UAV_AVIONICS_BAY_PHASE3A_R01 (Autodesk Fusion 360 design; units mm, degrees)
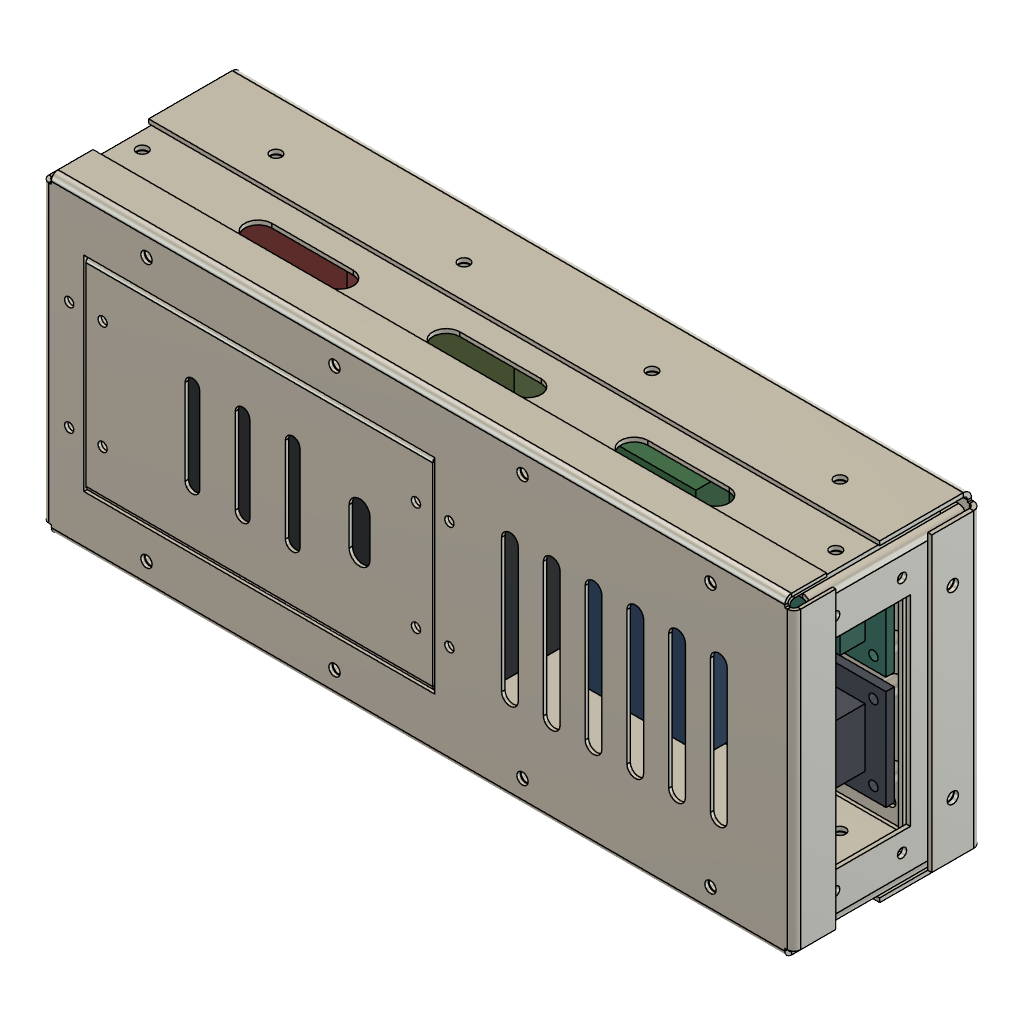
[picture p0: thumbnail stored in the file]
part number: 2026-11-24-00-04-00-130
part number: 2026-11-24-00-04-00-335
part number: 2026-11-24-00-04-00-357
part number: 2026-11-24-00-04-00-366
part number: 2026-11-24-00-04-00-376
part number: 2026-11-24-00-04-00-385
part number: 2026-11-24-00-04-00-395
part number: 2026-11-24-00-04-00-403
part number: 2026-11-24-00-04-00-413
part number: 2026-11-24-00-04-00-460
part number: 2026-11-24-00-04-01-313
part number: 2026-11-24-00-04-01-758
part number: 2026-11-24-00-04-02-270
part number: 2026-11-24-00-04-02-858
part number: 2026-11-24-00-04-03-521
part number: 2026-11-24-00-04-04-556
part number: 2026-11-24-00-04-05-190
part number: 2026-11-24-00-04-05-589
part number: 2026-11-24-00-04-06-393
part number: 2026-11-24-00-04-06-725
parameter "BAY_LENGTH" = 180 comment "[Assumption] Concept avionics bay overall outer length (X)"
parameter "BAY_WIDTH" = 75 comment "[Assumption] Concept avionics bay overall outer width (Y)"
parameter "BAY_HEIGHT" = 45 comment "[Assumption] Concept avionics bay overall outer height (Z)"
parameter "TRAY_FLANGE_H" = 22 comment "[Preliminary] Base tray perimeter upward flange height"
parameter "COVER_SKIRT_H" = 10 comment "[Preliminary] Top cover downward perimeter skirt height"
parameter "FORWARD_ZONE_END_X" = 94 comment "[Preliminary] X-boundary separating battery zone and aft deck"
parameter "HATCH_LENGTH" = 84 comment "[Preliminary] Service access hatch opening length"
parameter "HATCH_WIDTH" = 49 comment "[Preliminary] Service access hatch opening width"
parameter "T_BASE_TRAY" = 1 comment "[Preliminary] Main folded base tray thickness"
parameter "T_TOP_COVER" = 0.8 comment "[Preliminary] Removable top cover thickness"
parameter "T_ACCESS_HATCH" = 0.8 comment "[Preliminary] Service access hatch thickness"
parameter "T_SIDE_RAIL" = 1 comment "[Preliminary] Left and right side support rails thickness"
parameter "T_BULKHEAD" = 1 comment "[Preliminary] Front, rear, and connector bulkheads thickness"
parameter "T_EQUIP_DECK" = 1 comment "[Preliminary] Removable internal equipment deck thickness"
parameter "T_BRACKET" = 1 comment "[Preliminary] Structural and retention brackets thickness"
parameter "T_CABLE_CH" = 0.8 comment "[Preliminary] Cable routing channel and clamp thickness"
parameter "BEND_R_1_0" = 1 comment "[Preliminary] Inside bend radius for 1.0 mm Al 5052-H32"
parameter "BEND_R_0_8" = 0.8 comment "[Preliminary] Inside bend radius for 0.8 mm Al 5052-H32"
parameter "RELIEF_W_1_0" = 1.5 comment "[Preliminary] Bend relief width for 1.0 mm sheet"
parameter "RELIEF_D_1_0" = 2.5 comment "[Preliminary] Bend relief depth for 1.0 mm sheet"
parameter "RELIEF_W_0_8" = 1.2 comment "[Preliminary] Bend relief width for 0.8 mm sheet"
parameter "RELIEF_D_0_8" = 2.1 comment "[Preliminary] Bend relief depth for 0.8 mm sheet"
parameter "HOLE_CLR_M2_0" = 2.2 comment "[Preliminary] M2.0 medium clearance hole diameter"
parameter "HOLE_CLR_M2_5" = 2.7 comment "[Preliminary] M2.5 medium clearance hole diameter"
parameter "HOLE_CLR_M3_0" = 3.4 comment "[Preliminary] M3.0 medium clearance hole diameter"
parameter "HEAD_DIA_M2_0" = 3.8 comment "[Preliminary] ISO 4762/7380 M2.0 head diameter"
parameter "HEAD_DIA_M2_5" = 4.5 comment "[Preliminary] ISO 4762/7380 M2.5 head diameter"
parameter "STANDOFF_DECK_H" = 6 comment "[Preliminary] Under-deck plenum standoff height"
parameter "STANDOFF_PCB_H" = 4 comment "[Preliminary] PCB mounting standoff height"
parameter "ISO_PAD_THICK" = 2 comment "[Preliminary] Battery elastomer isolation pad thickness"
parameter "CLR_EQUIP_WALL" = 2 comment "[Preliminary] Minimum clearance between electronics and walls"
parameter "CLR_COMPONENT" = 1.5 comment "[Preliminary] General minimum clearance between adjacent parts"
parameter "CLR_SLIP_FIT" = 0.25 comment "[Preliminary] Per-side slip clearance for nested sheet metal parts"
parameter "CLR_COVER_FIT" = 0.3 comment "[Preliminary] Per-side clearance between cover skirt and chassis"
parameter "CLR_HATCH_GAP" = 0.5 comment "[Preliminary] Perimeter gap around removable service hatch"
parameter "d37" = 2
parameter "d38" = 1
parameter "d39" = 0.8
sketch "SK_Base_Tray_Blank" plane through (0, 0, 0) normal (0, 0, 1) x axis (1, 0, 0)
  line L1 (177.5, -37.5) -> (2.5, -37.5)
  line L2 (177.5, -35) -> (177.5, -37.5)
  line L3 (180, -35) -> (177.5, -35)
  line L4 (180, 35) -> (180, -35)
  line L5 (177.5, 35) -> (180, 35)
  line L6 (177.5, 37.5) -> (177.5, 35)
  line L7 (2.5, 37.5) -> (177.5, 37.5)
  line L8 (2.5, 35) -> (2.5, 37.5)
  line L9 (0, 35) -> (2.5, 35)
  line L10 (0, -35) -> (0, 35)
  line L11 (2.5, -35) -> (0, -35)
  line L12 (2.5, -37.5) -> (2.5, -35)
face "BaseFlange1" sketch "SK_Base_Tray_Blank"
face "EdgeFlange2" FlangeHeight 22 FlangeAngle 90
face "EdgeFlange3" FlangeHeight 12 FlangeAngle 90
sketch "SK_Base_Tray_Floor_Cutouts" plane through (0, 0, 0) normal (0, 0, 1) x axis (1, 0, 0)
  line L1 (27.3, -24.3) -> (22.7, -24.3)
  line L2 (22.7, -27.7) -> (27.3, -27.7)
  line L3 (27.3, 27.7) -> (22.7, 27.7)
  line L4 (22.7, 24.3) -> (27.3, 24.3)
  line L5 (157.3, -24.3) -> (152.7, -24.3)
  line L6 (152.7, -27.7) -> (157.3, -27.7)
  line L7 (157.3, 27.7) -> (152.7, 27.7)
  line L8 (152.7, 24.3) -> (157.3, 24.3)
  line L9 (64.5, -11.5) -> (35.5, -11.5)
  line L10 (35.5, -18.5) -> (64.5, -18.5)
  line L11 (149.5, 3.5) -> (120.5, 3.5)
  line L12 (120.5, -3.5) -> (149.5, -3.5)
  arc A1 centre (27.3, -26) radius 1.7 clockwise from (27.3, -24.3) to (27.3, -27.7)
  arc A2 centre (22.7, -26) radius 1.7 clockwise from (22.7, -27.7) to (22.7, -24.3)
  arc A3 centre (27.3, 26) radius 1.7 clockwise from (27.3, 27.7) to (27.3, 24.3)
  arc A4 centre (22.7, 26) radius 1.7 clockwise from (22.7, 24.3) to (22.7, 27.7)
  arc A5 centre (157.3, -26) radius 1.7 clockwise from (157.3, -24.3) to (157.3, -27.7)
  arc A6 centre (152.7, -26) radius 1.7 clockwise from (152.7, -27.7) to (152.7, -24.3)
  arc A7 centre (157.3, 26) radius 1.7 clockwise from (157.3, 27.7) to (157.3, 24.3)
  arc A8 centre (152.7, 26) radius 1.7 clockwise from (152.7, 24.3) to (152.7, 27.7)
  circle C1 centre (99, -29) radius 1.35
  circle C2 centre (99, 29) radius 1.35
  circle C3 centre (166, -29) radius 1.35
  circle C4 centre (166, 29) radius 1.35
  circle C5 centre (14, -27) radius 1.35
  circle C6 centre (14, -3) radius 1.35
  circle C7 centre (86, -27) radius 1.35
  circle C8 centre (86, -3) radius 1.35
  circle C9 centre (13, 11) radius 1.1
  circle C10 centre (13, 27) radius 1.1
  circle C11 centre (45, 11) radius 1.1
  circle C12 centre (45, 27) radius 1.1
  circle C13 centre (57, 11) radius 1.1
  circle C14 centre (57, 27) radius 1.1
  circle C15 centre (85, 11) radius 1.1
  circle C16 centre (85, 27) radius 1.1
  arc A9 centre (64.5, -15) radius 3.5 clockwise from (64.5, -11.5) to (64.5, -18.5)
  arc A10 centre (35.5, -15) radius 3.5 clockwise from (35.5, -18.5) to (35.5, -11.5)
  arc A11 centre (149.5, 0) radius 3.5 clockwise from (149.5, 3.5) to (149.5, -3.5)
  arc A12 centre (120.5, 0) radius 3.5 clockwise from (120.5, -3.5) to (120.5, 3.5)
extrude "Extrude1" cut sketch "SK_Base_Tray_Floor_Cutouts" distance 2
work_plane "WorkPlane1" AlongDistance -37.5 ExtraOffset 0
sketch "SK_Tray_Left_Wall_Holes" plane through (0, -37.5, 0) normal (0, 1, 0) x axis (1, 0, 0)
  circle C1 centre (25, -14) radius 1.35
  circle C2 centre (70, -14) radius 1.35
  circle C3 centre (115, -14) radius 1.35
  circle C4 centre (160, -14) radius 1.35
extrude "Extrude2" cut sketch "SK_Tray_Left_Wall_Holes" distance 2
work_plane "WorkPlane2" AlongDistance 37.5 ExtraOffset 0
sketch "SK_Tray_Right_Wall_Holes" plane through (0, 37.5, 0) normal (0, 1, 0) x axis (1, 0, 0)
  circle C1 centre (25, -14) radius 1.35
  circle C2 centre (70, -14) radius 1.35
  circle C3 centre (115, -14) radius 1.35
  circle C4 centre (160, -14) radius 1.35
extrude "Extrude3" cut sketch "SK_Tray_Right_Wall_Holes" distance 2
sketch "SK_Tray_Front_Lip_Holes" plane through (0, 0, 0) normal (1, 0, 0) x axis (0, 0, -1)
  circle C1 centre (-7, -22) radius 1.35
  circle C2 centre (-7, 22) radius 1.35
extrude "Extrude4" cut sketch "SK_Tray_Front_Lip_Holes" distance 2
work_plane "WorkPlane3" AlongDistance 180 ExtraOffset 0
sketch "SK_Tray_Rear_Lip_Holes" plane through (180, 0, 0) normal (1, 0, 0) x axis (0, 0, -1)
  circle C1 centre (-7, -22) radius 1.35
  circle C2 centre (-7, 22) radius 1.35
extrude "Extrude5" cut sketch "SK_Tray_Rear_Lip_Holes" distance 2
work_plane "WorkPlane1" AlongDistance -36.35 ExtraOffset 0
sketch "SK_PDB-01-102_Left_Side_Rail_Web" plane through (0, -36.35, 0) normal (0, 1, 0) x axis (1, 0, 0)
  line L1 (177, -7) -> (3, -7)
  line L2 (177, -44) -> (177, -7)
  line L3 (3, -44) -> (177, -44)
  line L4 (3, -7) -> (3, -44)
face "BaseFlange1" sketch "SK_PDB-01-102_Left_Side_Rail_Web"
face "EdgeFlange2" FlangeHeight 9 FlangeAngle 90
sketch "SK_PDB-01-102_Left_Side_Rail_Web_Features" plane through (0, -36.35, 0) normal (0, 1, 0) x axis (1, 0, 0)
  line L1 (57.25, -34.25) -> (37.75, -34.25)
  line L2 (37.75, -27.75) -> (57.25, -27.75)
  line L3 (102.25, -34.25) -> (82.75, -34.25)
  line L4 (82.75, -27.75) -> (102.25, -27.75)
  line L5 (147.25, -34.25) -> (127.75, -34.25)
  line L6 (127.75, -27.75) -> (147.25, -27.75)
  circle C1 centre (25, -14) radius 1.35
  circle C2 centre (70, -14) radius 1.35
  circle C3 centre (115, -14) radius 1.35
  circle C4 centre (160, -14) radius 1.35
  circle C5 centre (7, -28) radius 1.35
  circle C6 centre (173, -28) radius 1.35
  arc A1 centre (57.25, -31) radius 3.25 clockwise from (57.25, -27.75) to (57.25, -34.25)
  arc A2 centre (37.75, -31) radius 3.25 clockwise from (37.75, -34.25) to (37.75, -27.75)
  arc A3 centre (102.25, -31) radius 3.25 clockwise from (102.25, -27.75) to (102.25, -34.25)
  arc A4 centre (82.75, -31) radius 3.25 clockwise from (82.75, -34.25) to (82.75, -27.75)
  arc A5 centre (147.25, -31) radius 3.25 clockwise from (147.25, -27.75) to (147.25, -34.25)
  arc A6 centre (127.75, -31) radius 3.25 clockwise from (127.75, -34.25) to (127.75, -27.75)
extrude "Extrude1" cut sketch "SK_PDB-01-102_Left_Side_Rail_Web_Features" distance 2
work_plane "WorkPlane2" AlongDistance 44 ExtraOffset 0
sketch "SK_PDB-01-102_Left_Side_Rail_Top_Holes" plane through (0, 0, 44) normal (0, 0, 1) x axis (1, 0, 0)
  circle C1 centre (25, -31.5) radius 1.35
  circle C2 centre (70, -31.5) radius 1.35
  circle C3 centre (115, -31.5) radius 1.35
  circle C4 centre (160, -31.5) radius 1.35
extrude "Extrude2" cut sketch "SK_PDB-01-102_Left_Side_Rail_Top_Holes" distance 2
work_plane "WorkPlane1" AlongDistance 36.35 ExtraOffset 0
sketch "SK_PDB-01-103_Right_Side_Rail_Web" plane through (0, 36.35, 0) normal (0, 1, 0) x axis (1, 0, 0)
  line L1 (177, -7) -> (3, -7)
  line L2 (177, -44) -> (177, -7)
  line L3 (3, -44) -> (177, -44)
  line L4 (3, -7) -> (3, -44)
face "BaseFlange2" sketch "SK_PDB-01-103_Right_Side_Rail_Web"
face "EdgeFlange3" FlangeHeight 9 FlangeAngle 90
sketch "SK_PDB-01-103_Right_Side_Rail_Web_Features" plane through (0, 36.35, 0) normal (0, 1, 0) x axis (1, 0, 0)
  line L1 (57.25, -34.25) -> (37.75, -34.25)
  line L2 (37.75, -27.75) -> (57.25, -27.75)
  line L3 (102.25, -34.25) -> (82.75, -34.25)
  line L4 (82.75, -27.75) -> (102.25, -27.75)
  line L5 (147.25, -34.25) -> (127.75, -34.25)
  line L6 (127.75, -27.75) -> (147.25, -27.75)
  circle C1 centre (25, -14) radius 1.35
  circle C2 centre (70, -14) radius 1.35
  circle C3 centre (115, -14) radius 1.35
  circle C4 centre (160, -14) radius 1.35
  circle C5 centre (7, -28) radius 1.35
  circle C6 centre (173, -28) radius 1.35
  arc A1 centre (57.25, -31) radius 3.25 clockwise from (57.25, -27.75) to (57.25, -34.25)
  arc A2 centre (37.75, -31) radius 3.25 clockwise from (37.75, -34.25) to (37.75, -27.75)
  arc A3 centre (102.25, -31) radius 3.25 clockwise from (102.25, -27.75) to (102.25, -34.25)
  arc A4 centre (82.75, -31) radius 3.25 clockwise from (82.75, -34.25) to (82.75, -27.75)
  arc A5 centre (147.25, -31) radius 3.25 clockwise from (147.25, -27.75) to (147.25, -34.25)
  arc A6 centre (127.75, -31) radius 3.25 clockwise from (127.75, -34.25) to (127.75, -27.75)
extrude "Extrude1" cut sketch "SK_PDB-01-103_Right_Side_Rail_Web_Features" distance 2
work_plane "WorkPlane2" AlongDistance 44 ExtraOffset 0
sketch "SK_PDB-01-103_Right_Side_Rail_Top_Holes" plane through (0, 0, 44) normal (0, 0, 1) x axis (1, 0, 0)
  circle C1 centre (25, 31.5) radius 1.35
  circle C2 centre (70, 31.5) radius 1.35
  circle C3 centre (115, 31.5) radius 1.35
  circle C4 centre (160, 31.5) radius 1.35
extrude "Extrude2" cut sketch "SK_PDB-01-103_Right_Side_Rail_Top_Holes" distance 2
work_plane "WorkPlane1" AlongDistance 1.15 ExtraOffset 0
sketch "SK_Front_Bulkhead_Blank" plane through (1.15, 0, 0) normal (1, 0, 0) x axis (0, 0, -1)
  line L1 (-2.5, 35.2) -> (-2.5, -35.2)
  line L2 (-39.8, 35.2) -> (-2.5, 35.2)
  line L3 (-39.8, 32.2) -> (-39.8, 35.2)
  line L4 (-42.8, 32.2) -> (-39.8, 32.2)
  line L5 (-42.8, -32.2) -> (-42.8, 32.2)
  line L6 (-39.8, -32.2) -> (-42.8, -32.2)
  line L7 (-39.8, -35.2) -> (-39.8, -32.2)
  line L8 (-2.5, -35.2) -> (-39.8, -35.2)
face "BaseFlange1" sketch "SK_Front_Bulkhead_Blank"
face "EdgeFlange2" FlangeHeight 10 FlangeAngle 90
face "EdgeFlange3" FlangeHeight 8 FlangeAngle 90
sketch "SK_Front_Bulkhead_Cutouts" plane through (1.15, 0, 0) normal (1, 0, 0) x axis (0, 0, -1)
  line L1 (-26.5, -16.5) -> (-26.5, -23.5)
  line L2 (-21.5, -23.5) -> (-21.5, -16.5)
  line L3 (-26.5, 23.5) -> (-26.5, 16.5)
  line L4 (-21.5, 16.5) -> (-21.5, 23.5)
  circle C1 centre (-7, -22) radius 1.35
  circle C2 centre (-7, 22) radius 1.35
  circle C3 centre (-24, 0) radius 5
  circle C4 centre (-24, -9) radius 1.1
  circle C5 centre (-24, 9) radius 1.1
  arc A1 centre (-24, -16.5) radius 2.5 clockwise from (-26.5, -16.5) to (-21.5, -16.5)
  arc A2 centre (-24, -23.5) radius 2.5 clockwise from (-21.5, -23.5) to (-26.5, -23.5)
  arc A3 centre (-24, 23.5) radius 2.5 clockwise from (-26.5, 23.5) to (-21.5, 23.5)
  arc A4 centre (-24, 16.5) radius 2.5 clockwise from (-21.5, 16.5) to (-26.5, 16.5)
extrude "Extrude1" cut sketch "SK_Front_Bulkhead_Cutouts" distance 2
work_plane "WorkPlane2" AlongDistance -35.2 ExtraOffset 0
sketch "SK_Front_Left_Hole" plane through (0, -35.2, 0) normal (0, 1, 0) x axis (1, 0, 0)
  circle C1 centre (7, -28) radius 1.35
extrude "Extrude2" cut sketch "SK_Front_Left_Hole" distance 2
work_plane "WorkPlane3" AlongDistance 35.2 ExtraOffset 0
sketch "SK_Front_Right_Hole" plane through (0, 35.2, 0) normal (0, 1, 0) x axis (1, 0, 0)
  circle C1 centre (7, -28) radius 1.35
extrude "Extrude3" cut sketch "SK_Front_Right_Hole" distance 2
work_plane "WorkPlane1" AlongDistance 178.85 ExtraOffset 0
sketch "SK_Rear_Bulkhead_Blank" plane through (178.85, 0, 0) normal (1, 0, 0) x axis (0, 0, -1)
  line L1 (-2.5, 35.2) -> (-2.5, -35.2)
  line L2 (-39.8, 35.2) -> (-2.5, 35.2)
  line L3 (-39.8, 32.2) -> (-39.8, 35.2)
  line L4 (-42.8, 32.2) -> (-39.8, 32.2)
  line L5 (-42.8, -32.2) -> (-42.8, 32.2)
  line L6 (-39.8, -32.2) -> (-42.8, -32.2)
  line L7 (-39.8, -35.2) -> (-39.8, -32.2)
  line L8 (-2.5, -35.2) -> (-39.8, -35.2)
face "BaseFlange2" sketch "SK_Rear_Bulkhead_Blank"
face "EdgeFlange3" FlangeHeight 10 FlangeAngle 90
face "EdgeFlange4" FlangeHeight 8 FlangeAngle 90
sketch "SK_Rear_Bulkhead_Cutouts" plane through (178.85, 0, 0) normal (1, 0, 0) x axis (0, 0, -1)
  line L1 (-16, 24) -> (-16, -24)
  line L2 (-36, 24) -> (-16, 24)
  line L3 (-36, -24) -> (-36, 24)
  line L4 (-16, -24) -> (-36, -24)
  circle C1 centre (-7, -22) radius 1.35
  circle C2 centre (-7, 22) radius 1.35
  circle C3 centre (-18, -28.5) radius 1.1
  circle C4 centre (-34, -28.5) radius 1.1
  circle C5 centre (-18, 28.5) radius 1.1
  circle C6 centre (-34, 28.5) radius 1.1
extrude "Extrude1" cut sketch "SK_Rear_Bulkhead_Cutouts" distance 2
work_plane "WorkPlane2" AlongDistance -35.2 ExtraOffset 0
sketch "SK_Rear_Left_Hole" plane through (0, -35.2, 0) normal (0, 1, 0) x axis (1, 0, 0)
  circle C1 centre (173, -28) radius 1.35
extrude "Extrude2" cut sketch "SK_Rear_Left_Hole" distance 2
work_plane "WorkPlane3" AlongDistance 35.2 ExtraOffset 0
sketch "SK_Rear_Right_Hole" plane through (0, 35.2, 0) normal (0, 1, 0) x axis (1, 0, 0)
  circle C1 centre (173, -28) radius 1.35
extrude "Extrude3" cut sketch "SK_Rear_Right_Hole" distance 2
work_plane "WorkPlane1" AlongDistance 45 ExtraOffset 0
sketch "SK_Top_Cover_Blank" plane through (0, 0, 45) normal (0, 0, 1) x axis (1, 0, 0)
  line L1 (177.8, -37.5) -> (2.2, -37.5)
  line L2 (177.8, -35.3) -> (177.8, -37.5)
  line L3 (180, -35.3) -> (177.8, -35.3)
  line L4 (180, 35.3) -> (180, -35.3)
  line L5 (177.8, 35.3) -> (180, 35.3)
  line L6 (177.8, 37.5) -> (177.8, 35.3)
  line L7 (2.2, 37.5) -> (177.8, 37.5)
  line L8 (2.2, 35.3) -> (2.2, 37.5)
  line L9 (0, 35.3) -> (2.2, 35.3)
  line L10 (0, -35.3) -> (0, 35.3)
  line L11 (2.2, -35.3) -> (0, -35.3)
  line L12 (2.2, -37.5) -> (2.2, -35.3)
face "BaseFlange2" sketch "SK_Top_Cover_Blank"
face "EdgeFlange3" FlangeHeight 10 FlangeAngle 90
face "EdgeFlange4" FlangeHeight 10 FlangeAngle 90
sketch "SK_Top_Cover_Cutouts" plane through (0, 0, 45) normal (0, 0, 1) x axis (1, 0, 0)
  line L1 (94, -24.5) -> (10, -24.5)
  line L2 (94, 24.5) -> (94, -24.5)
  line L3 (10, 24.5) -> (94, 24.5)
  line L4 (10, -24.5) -> (10, 24.5)
  line L5 (114, 16) -> (114, -16)
  line L6 (110, -16) -> (110, 16)
  line L7 (124, 16) -> (124, -16)
  line L8 (120, -16) -> (120, 16)
  line L9 (134, 16) -> (134, -16)
  line L10 (130, -16) -> (130, 16)
  line L11 (144, 16) -> (144, -16)
  line L12 (140, -16) -> (140, 16)
  line L13 (154, 16) -> (154, -16)
  line L14 (150, -16) -> (150, 16)
  line L15 (164, 16) -> (164, -16)
  line L16 (160, -16) -> (160, 16)
  circle C1 centre (25, -31.5) radius 1.35
  circle C2 centre (25, 31.5) radius 1.35
  circle C3 centre (70, -31.5) radius 1.35
  circle C4 centre (70, 31.5) radius 1.35
  circle C5 centre (115, -31.5) radius 1.35
  circle C6 centre (115, 31.5) radius 1.35
  circle C7 centre (160, -31.5) radius 1.35
  circle C8 centre (160, 31.5) radius 1.35
  circle C9 centre (6.5, -13) radius 1.1
  circle C10 centre (6.5, 13) radius 1.1
  circle C11 centre (97.5, -13) radius 1.1
  circle C12 centre (97.5, 13) radius 1.1
  arc A1 centre (112, 16) radius 2 clockwise from (110, 16) to (114, 16)
  arc A2 centre (112, -16) radius 2 clockwise from (114, -16) to (110, -16)
  arc A3 centre (122, 16) radius 2 clockwise from (120, 16) to (124, 16)
  arc A4 centre (122, -16) radius 2 clockwise from (124, -16) to (120, -16)
  arc A5 centre (132, 16) radius 2 clockwise from (130, 16) to (134, 16)
  arc A6 centre (132, -16) radius 2 clockwise from (134, -16) to (130, -16)
  arc A7 centre (142, 16) radius 2 clockwise from (140, 16) to (144, 16)
  arc A8 centre (142, -16) radius 2 clockwise from (144, -16) to (140, -16)
  arc A9 centre (152, 16) radius 2 clockwise from (150, 16) to (154, 16)
  arc A10 centre (152, -16) radius 2 clockwise from (154, -16) to (150, -16)
  arc A11 centre (162, 16) radius 2 clockwise from (160, 16) to (164, 16)
  arc A12 centre (162, -16) radius 2 clockwise from (164, -16) to (160, -16)
extrude "Extrude1" cut sketch "SK_Top_Cover_Cutouts" distance 2
work_plane "WorkPlane1" AlongDistance 45 ExtraOffset 0
sketch "SK_Access_Hatch_Blank" plane through (0, 0, 45) normal (0, 0, 1) x axis (1, 0, 0)
  line L1 (93.5, -24) -> (10.5, -24)
  line L2 (93.5, 24) -> (93.5, -24)
  line L3 (10.5, 24) -> (93.5, 24)
  line L4 (10.5, -24) -> (10.5, 24)
face "BaseFlange2" sketch "SK_Access_Hatch_Blank"
face "Hem3" HemGap 0.02 HemLength 4.5
face "Hem4" HemGap 0.02 HemLength 4.5
sketch "SK_Access_Hatch_Cutouts" plane through (0, 0, 45) normal (0, 0, 1) x axis (1, 0, 0)
  line L1 (37.75, 10.25) -> (37.75, -10.25)
  line L2 (34.25, -10.25) -> (34.25, 10.25)
  line L3 (49.75, 10.25) -> (49.75, -10.25)
  line L4 (46.25, -10.25) -> (46.25, 10.25)
  line L5 (61.75, 10.25) -> (61.75, -10.25)
  line L6 (58.25, -10.25) -> (58.25, 10.25)
  line L7 (78.5, 4.5) -> (78.5, -4.5)
  line L8 (73.5, -4.5) -> (73.5, 4.5)
  circle C1 centre (14.5, -13) radius 1.1
  circle C2 centre (14.5, 13) radius 1.1
  circle C3 centre (89.5, -13) radius 1.1
  circle C4 centre (89.5, 13) radius 1.1
  arc A1 centre (36, 10.25) radius 1.75 clockwise from (34.25, 10.25) to (37.75, 10.25)
  arc A2 centre (36, -10.25) radius 1.75 clockwise from (37.75, -10.25) to (34.25, -10.25)
  arc A3 centre (48, 10.25) radius 1.75 clockwise from (46.25, 10.25) to (49.75, 10.25)
  arc A4 centre (48, -10.25) radius 1.75 clockwise from (49.75, -10.25) to (46.25, -10.25)
  arc A5 centre (60, 10.25) radius 1.75 clockwise from (58.25, 10.25) to (61.75, 10.25)
  arc A6 centre (60, -10.25) radius 1.75 clockwise from (61.75, -10.25) to (58.25, -10.25)
  arc A7 centre (76, 4.5) radius 2.5 clockwise from (73.5, 4.5) to (78.5, 4.5)
  arc A8 centre (76, -4.5) radius 2.5 clockwise from (78.5, -4.5) to (73.5, -4.5)
extrude "Extrude1" cut sketch "SK_Access_Hatch_Cutouts" distance 2
work_plane "WorkPlane1" AlongDistance 44.2 ExtraOffset 0
sketch "SK_Retainer_Strip_Blank" plane through (0, 0, 44.2) normal (0, 0, 1) x axis (1, 0, 0)
  line L1 (18, -18) -> (3, -18)
  line L2 (18, 18) -> (18, -18)
  line L3 (3, 18) -> (18, 18)
  line L4 (3, -18) -> (3, 18)
face "BaseFlange2" sketch "SK_Retainer_Strip_Blank"
sketch "SK_Retainer_Strip_Holes" plane through (0, 0, 44.2) normal (0, 0, 1) x axis (1, 0, 0)
  circle C1 centre (6.5, -13) radius 1.1
  circle C2 centre (6.5, 13) radius 1.1
  circle C3 centre (14.5, -13) radius 1.1
  circle C4 centre (14.5, 13) radius 1.1
extrude "Extrude1" cut sketch "SK_Retainer_Strip_Holes" distance 2
copy_paste "CopyPaste1"
work_plane "WorkPlane1" AlongDistance 7 ExtraOffset 0
sketch "SK_Equipment_Deck_Blank" plane through (0, 0, 7) normal (0, 0, 1) x axis (1, 0, 0)
  line L1 (174, -33.5) -> (94, -33.5)
  line L2 (174, 33.5) -> (174, -33.5)
  line L3 (94, 33.5) -> (174, 33.5)
  line L4 (94, -33.5) -> (94, 33.5)
face "BaseFlange1" sketch "SK_Equipment_Deck_Blank"
face "EdgeFlange2" FlangeHeight 6 FlangeAngle 90
sketch "SK_Equipment_Deck_Cutouts" plane through (0, 0, 7) normal (0, 0, 1) x axis (1, 0, 0)
  line L1 (131.5, -10) -> (115.5, -10)
  line L2 (115.5, -16) -> (131.5, -16)
  line L3 (144.75, 23) -> (144.75, 11)
  line L4 (140.75, 11) -> (140.75, 23)
  circle C1 centre (99, -29) radius 1.35
  circle C2 centre (99, 29) radius 1.35
  circle C3 centre (166, -29) radius 1.35
  circle C4 centre (166, 29) radius 1.35
  circle C5 centre (106, -28) radius 1.1
  circle C6 centre (106, 2) radius 1.1
  circle C7 centre (141, -28) radius 1.1
  circle C8 centre (141, 2) radius 1.1
  circle C9 centre (105.5, 12) radius 1.1
  circle C10 centre (105.5, 28) radius 1.1
  circle C11 centre (135.5, 12) radius 1.1
  circle C12 centre (135.5, 28) radius 1.1
  circle C13 centre (150, -22) radius 1.1
  circle C14 centre (150, -4) radius 1.1
  circle C15 centre (168, -22) radius 1.1
  circle C16 centre (168, -4) radius 1.1
  circle C17 centre (150, 5) radius 1.1
  circle C18 centre (150, 23) radius 1.1
  circle C19 centre (168, 5) radius 1.1
  circle C20 centre (168, 23) radius 1.1
  arc A1 centre (131.5, -13) radius 3 clockwise from (131.5, -10) to (131.5, -16)
  arc A2 centre (115.5, -13) radius 3 clockwise from (115.5, -16) to (115.5, -10)
  arc A3 centre (142.75, 23) radius 2 clockwise from (140.75, 23) to (144.75, 23)
  arc A4 centre (142.75, 11) radius 2 clockwise from (144.75, 11) to (140.75, 11)
extrude "Extrude1" cut sketch "SK_Equipment_Deck_Cutouts" distance 2
sketch "SK_PCB_Clamp_Blank" plane through (0, 0, 0) normal (0, 0, 1) x axis (1, 0, 0)
  line L1 (3, -17.5) -> (-4, -17.5)
  line L2 (3, 17.5) -> (3, -17.5)
  line L3 (-4, 17.5) -> (3, 17.5)
  line L4 (-4, -17.5) -> (-4, 17.5)
face "BaseFlange1" sketch "SK_PCB_Clamp_Blank"
face "EdgeFlange2" FlangeHeight 6 FlangeAngle 90
sketch "SK_PCB_Clamp_Holes" plane through (0, 0, 0) normal (0, 0, 1) x axis (1, 0, 0)
  circle C1 centre (0, -15) radius 1.1
  circle C2 centre (0, 15) radius 1.1
extrude "Extrude1" cut sketch "SK_PCB_Clamp_Holes" distance 2
copy_paste "CopyPaste1"
place_component sketch "SK_PDB-03-303_Deck_Standoff_M2_5x6_Body"
sketch "SK_PDB-03-303_Deck_Standoff_M2_5x6_Body" plane through (0, 0, 0) normal (0, 0, 1) x axis (1, 0, 0)
  circle C1 centre (0, 0) radius 2.5
  circle C2 centre (0, 0) radius 1.3
extrude "Extrude1" new body sketch "SK_PDB-03-303_Deck_Standoff_M2_5x6_Body" along normal blind 6
copy_paste "CopyPaste2"
copy_paste "CopyPaste3"
copy_paste "CopyPaste4"
place_component sketch "SK_PDB-03-304_PCB_Standoff_M2x4_Body"
sketch "SK_PDB-03-304_PCB_Standoff_M2x4_Body" plane through (0, 0, 0) normal (0, 0, 1) x axis (1, 0, 0)
  circle C1 centre (0, 0) radius 2
  circle C2 centre (0, 0) radius 1.05
extrude "Extrude1" new body sketch "SK_PDB-03-304_PCB_Standoff_M2x4_Body" along normal blind 4
copy_paste "CopyPaste5"
copy_paste "CopyPaste6"
copy_paste "CopyPaste7"
copy_paste "CopyPaste8"
copy_paste "CopyPaste9"
copy_paste "CopyPaste10"
copy_paste "CopyPaste11"
copy_paste "CopyPaste12"
copy_paste "CopyPaste13"
copy_paste "CopyPaste14"
copy_paste "CopyPaste15"
copy_paste "CopyPaste16"
copy_paste "CopyPaste17"
copy_paste "CopyPaste18"
copy_paste "CopyPaste19"
copy_paste "CopyPaste20"
copy_paste "CopyPaste21"
copy_paste "CopyPaste22"
copy_paste "CopyPaste23"
copy_paste "CopyPaste24"
copy_paste "CopyPaste25"
copy_paste "CopyPaste26"
copy_paste "CopyPaste27"
work_plane "WorkPlane1" AlongDistance 5 ExtraOffset 0
sketch "SK_PCB_Substrate" plane through (0, 0, 5) normal (0, 0, 1) x axis (1, 0, 0)
  line L1 (48, 8) -> (10, 8)
  line L2 (48, 30) -> (48, 8)
  line L3 (10, 30) -> (48, 30)
  line L4 (10, 8) -> (10, 30)
extrude "Extrude1" new body sketch "SK_PCB_Substrate" along normal blind 2
work_plane "WorkPlane2" AlongDistance 7 ExtraOffset 0
sketch "SK_Module_Housing" plane through (0, 0, 7) normal (0, 0, 1) x axis (1, 0, 0)
  line L1 (43, 13) -> (15, 13)
  line L2 (43, 25) -> (43, 13)
  line L3 (15, 25) -> (43, 25)
  line L4 (15, 13) -> (15, 25)
extrude "Extrude2" add sketch "SK_Module_Housing" along normal blind 8
work_plane "WorkPlane3" AlongDistance 5 ExtraOffset 0
sketch "SK_PCB_Mount_Holes" plane through (0, 0, 5) normal (0, 0, 1) x axis (1, 0, 0)
  circle C1 centre (13, 11) radius 1.1
  circle C2 centre (13, 27) radius 1.1
  circle C3 centre (45, 11) radius 1.1
  circle C4 centre (45, 27) radius 1.1
extrude "Extrude3" cut sketch "SK_PCB_Mount_Holes" distance 3
work_plane "WorkPlane1" AlongDistance 5 ExtraOffset 0
sketch "SK_PCB_Substrate" plane through (0, 0, 5) normal (0, 0, 1) x axis (1, 0, 0)
  line L1 (88, 8) -> (54, 8)
  line L2 (88, 30) -> (88, 8)
  line L3 (54, 30) -> (88, 30)
  line L4 (54, 8) -> (54, 30)
extrude "Extrude1" new body sketch "SK_PCB_Substrate" along normal blind 2
work_plane "WorkPlane2" AlongDistance 7 ExtraOffset 0
sketch "SK_Module_Housing" plane through (0, 0, 7) normal (0, 0, 1) x axis (1, 0, 0)
  line L1 (83, 13) -> (59, 13)
  line L2 (83, 25) -> (83, 13)
  line L3 (59, 25) -> (83, 25)
  line L4 (59, 13) -> (59, 25)
extrude "Extrude2" add sketch "SK_Module_Housing" along normal blind 8
work_plane "WorkPlane3" AlongDistance 5 ExtraOffset 0
sketch "SK_PCB_Mount_Holes" plane through (0, 0, 5) normal (0, 0, 1) x axis (1, 0, 0)
  circle C1 centre (57, 11) radius 1.1
  circle C2 centre (57, 27) radius 1.1
  circle C3 centre (85, 11) radius 1.1
  circle C4 centre (85, 27) radius 1.1
extrude "Extrude3" cut sketch "SK_PCB_Mount_Holes" distance 3
work_plane "WorkPlane1" AlongDistance 12 ExtraOffset 0
sketch "SK_PCB_Substrate" plane through (0, 0, 12) normal (0, 0, 1) x axis (1, 0, 0)
  line L1 (144.5, -31) -> (102.5, -31)
  line L2 (144.5, 5) -> (144.5, -31)
  line L3 (102.5, 5) -> (144.5, 5)
  line L4 (102.5, -31) -> (102.5, 5)
extrude "Extrude1" new body sketch "SK_PCB_Substrate" along normal blind 2
work_plane "WorkPlane2" AlongDistance 14 ExtraOffset 0
sketch "SK_Module_Housing" plane through (0, 0, 14) normal (0, 0, 1) x axis (1, 0, 0)
  line L1 (137.5, -26) -> (109.5, -26)
  line L2 (137.5, 0) -> (137.5, -26)
  line L3 (109.5, 0) -> (137.5, 0)
  line L4 (109.5, -26) -> (109.5, 0)
extrude "Extrude2" add sketch "SK_Module_Housing" along normal blind 10
work_plane "WorkPlane3" AlongDistance 12 ExtraOffset 0
sketch "SK_PCB_Mount_Holes" plane through (0, 0, 12) normal (0, 0, 1) x axis (1, 0, 0)
  circle C1 centre (106, -28) radius 1.1
  circle C2 centre (106, 2) radius 1.1
  circle C3 centre (141, -28) radius 1.1
  circle C4 centre (141, 2) radius 1.1
extrude "Extrude3" cut sketch "SK_PCB_Mount_Holes" distance 3
work_plane "WorkPlane1" AlongDistance 12 ExtraOffset 0
sketch "SK_PCB_Substrate" plane through (0, 0, 12) normal (0, 0, 1) x axis (1, 0, 0)
  line L1 (138.5, 9) -> (102.5, 9)
  line L2 (138.5, 31) -> (138.5, 9)
  line L3 (102.5, 31) -> (138.5, 31)
  line L4 (102.5, 9) -> (102.5, 31)
extrude "Extrude1" new body sketch "SK_PCB_Substrate" along normal blind 2
work_plane "WorkPlane2" AlongDistance 14 ExtraOffset 0
sketch "SK_Module_Housing" plane through (0, 0, 14) normal (0, 0, 1) x axis (1, 0, 0)
  line L1 (133.5, 14) -> (107.5, 14)
  line L2 (133.5, 26) -> (133.5, 14)
  line L3 (107.5, 26) -> (133.5, 26)
  line L4 (107.5, 14) -> (107.5, 26)
extrude "Extrude2" add sketch "SK_Module_Housing" along normal blind 8
work_plane "WorkPlane3" AlongDistance 12 ExtraOffset 0
sketch "SK_PCB_Mount_Holes" plane through (0, 0, 12) normal (0, 0, 1) x axis (1, 0, 0)
  circle C1 centre (105.5, 12) radius 1.1
  circle C2 centre (105.5, 28) radius 1.1
  circle C3 centre (135.5, 12) radius 1.1
  circle C4 centre (135.5, 28) radius 1.1
extrude "Extrude3" cut sketch "SK_PCB_Mount_Holes" distance 3
work_plane "WorkPlane1" AlongDistance 12 ExtraOffset 0
sketch "SK_PCB_Substrate" plane through (0, 0, 12) normal (0, 0, 1) x axis (1, 0, 0)
  line L1 (171, -25) -> (147, -25)
  line L2 (171, -1) -> (171, -25)
  line L3 (147, -1) -> (171, -1)
  line L4 (147, -25) -> (147, -1)
extrude "Extrude1" new body sketch "SK_PCB_Substrate" along normal blind 2
work_plane "WorkPlane2" AlongDistance 14 ExtraOffset 0
sketch "SK_Module_Housing" plane through (0, 0, 14) normal (0, 0, 1) x axis (1, 0, 0)
  line L1 (166, -20) -> (152, -20)
  line L2 (166, -6) -> (166, -20)
  line L3 (152, -6) -> (166, -6)
  line L4 (152, -20) -> (152, -6)
extrude "Extrude2" add sketch "SK_Module_Housing" along normal blind 7
work_plane "WorkPlane3" AlongDistance 12 ExtraOffset 0
sketch "SK_PCB_Mount_Holes" plane through (0, 0, 12) normal (0, 0, 1) x axis (1, 0, 0)
  circle C1 centre (150, -22) radius 1.1
  circle C2 centre (150, -4) radius 1.1
  circle C3 centre (168, -22) radius 1.1
  circle C4 centre (168, -4) radius 1.1
extrude "Extrude3" cut sketch "SK_PCB_Mount_Holes" distance 3
work_plane "WorkPlane1" AlongDistance 12 ExtraOffset 0
sketch "SK_PCB_Substrate" plane through (0, 0, 12) normal (0, 0, 1) x axis (1, 0, 0)
  line L1 (171, 2) -> (147, 2)
  line L2 (171, 26) -> (171, 2)
  line L3 (147, 26) -> (171, 26)
  line L4 (147, 2) -> (147, 26)
extrude "Extrude1" new body sketch "SK_PCB_Substrate" along normal blind 2
work_plane "WorkPlane2" AlongDistance 14 ExtraOffset 0
sketch "SK_Module_Housing" plane through (0, 0, 14) normal (0, 0, 1) x axis (1, 0, 0)
  line L1 (166, 7) -> (152, 7)
  line L2 (166, 21) -> (166, 7)
  line L3 (152, 21) -> (166, 21)
  line L4 (152, 7) -> (152, 21)
extrude "Extrude2" add sketch "SK_Module_Housing" along normal blind 6
work_plane "WorkPlane3" AlongDistance 12 ExtraOffset 0
sketch "SK_PCB_Mount_Holes" plane through (0, 0, 12) normal (0, 0, 1) x axis (1, 0, 0)
  circle C1 centre (150, 5) radius 1.1
  circle C2 centre (150, 23) radius 1.1
  circle C3 centre (168, 5) radius 1.1
  circle C4 centre (168, 23) radius 1.1
extrude "Extrude3" cut sketch "SK_PCB_Mount_Holes" distance 3
work_plane "WorkPlane1" AlongDistance 3 ExtraOffset 0
sketch "SK_Battery_Envelope_Solid" plane through (0, 0, 3) normal (0, 0, 1) x axis (1, 0, 0)
  line L1 (92, -32) -> (8, -32)
  line L2 (92, 2) -> (92, -32)
  line L3 (8, 2) -> (92, 2)
  line L4 (8, -32) -> (8, 2)
extrude "Extrude1" new body sketch "SK_Battery_Envelope_Solid" along normal blind 24
sketch "SK_Battery_Cradle_Blank" plane through (0, 0, 0) normal (0, 0, 1) x axis (1, 0, 0)
  line L1 (4, -18.2) -> (-4, -18.2)
  line L2 (4, 18.2) -> (4, -18.2)
  line L3 (-4, 18.2) -> (4, 18.2)
  line L4 (-4, -18.2) -> (-4, 18.2)
face "BaseFlange1" sketch "SK_Battery_Cradle_Blank"
face "EdgeFlange2" FlangeHeight 27 FlangeAngle 90
sketch "SK_Cradle_Floor_Holes" plane through (0, 0, 0) normal (0, 0, 1) x axis (1, 0, 0)
  circle C1 centre (0, -12) radius 1.35
  circle C2 centre (0, 12) radius 1.35
extrude "Extrude1" cut sketch "SK_Cradle_Floor_Holes" distance 2
work_plane "WorkPlane1" AlongDistance -18.2 ExtraOffset 0
sketch "SK_Cradle_Left_Slot" plane through (0, -18.2, 0) normal (0, 1, 0) x axis (1, 0, 0)
  line L1 (1.6, -19.9) -> (1.6, -9.1)
  line L2 (-1.6, -9.1) -> (-1.6, -19.9)
  arc A1 centre (0, -19.9) radius 1.6 clockwise from (1.6, -19.9) to (-1.6, -19.9)
  arc A2 centre (0, -9.1) radius 1.6 clockwise from (-1.6, -9.1) to (1.6, -9.1)
extrude "Extrude2" cut sketch "SK_Cradle_Left_Slot" distance 2
work_plane "WorkPlane2" AlongDistance 18.2 ExtraOffset 0
sketch "SK_Cradle_Right_Slot" plane through (0, 18.2, 0) normal (0, 1, 0) x axis (1, 0, 0)
  line L1 (1.6, -19.9) -> (1.6, -9.1)
  line L2 (-1.6, -9.1) -> (-1.6, -19.9)
  arc A1 centre (0, -19.9) radius 1.6 clockwise from (1.6, -19.9) to (-1.6, -19.9)
  arc A2 centre (0, -9.1) radius 1.6 clockwise from (-1.6, -9.1) to (1.6, -9.1)
extrude "Extrude3" cut sketch "SK_Cradle_Right_Slot" distance 2
copy_paste "CopyPaste1"
work_plane "WorkPlane1" AlongDistance 1 ExtraOffset 0
sketch "SK_Isolation_Pad_Body" plane through (0, 0, 1) normal (0, 0, 1) x axis (1, 0, 0)
  line L1 (81, -31) -> (19, -31)
  line L2 (81, 1) -> (81, -31)
  line L3 (19, 1) -> (81, 1)
  line L4 (19, -31) -> (19, 1)
extrude "Extrude1" new body sketch "SK_Isolation_Pad_Body" along normal blind 2
work_plane "WorkPlane2" AlongDistance 1 ExtraOffset 0
sketch "SK_Iso_Pad_Vent_Slot" plane through (0, 0, 1) normal (0, 0, 1) x axis (1, 0, 0)
  line L1 (64, -12) -> (36, -12)
  line L2 (36, -18) -> (64, -18)
  arc A1 centre (64, -15) radius 3 clockwise from (64, -12) to (64, -18)
  arc A2 centre (36, -15) radius 3 clockwise from (36, -18) to (36, -12)
extrude "Extrude2" cut sketch "SK_Iso_Pad_Vent_Slot" distance 3
work_plane "WorkPlane1" AlongDistance -2.5 ExtraOffset 0
sketch "SK_Retention_Strap_U" plane through (-2.5, 0, 0) normal (1, 0, 0) x axis (0, 0, -1)
  line L1 (-13.5, -18.3) -> (-13.5, -19.3)
  line L2 (-27.2, -18.3) -> (-13.5, -18.3)
  line L3 (-27.2, 18.3) -> (-27.2, -18.3)
  line L4 (-13.5, 18.3) -> (-27.2, 18.3)
  line L5 (-13.5, 19.3) -> (-13.5, 18.3)
  line L6 (-28.2, 19.3) -> (-13.5, 19.3)
  line L7 (-28.2, -19.3) -> (-28.2, 19.3)
  line L8 (-13.5, -19.3) -> (-28.2, -19.3)
extrude "Extrude1" new body sketch "SK_Retention_Strap_U" along normal blind 5
copy_paste "CopyPaste2"
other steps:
create_component "CreateComponent1"
create_component "CreateComponent2"
create_component "CreateComponent3"
create_component "CreateComponent4"
create_component "CreateComponent5"
create_component "CreateComponent6"
create_component "CreateComponent7"
create_component "CreateComponent8"
create_component "CreateComponent1"
create_component "CreateComponent2"
create_component "CreateComponent3"
create_component "CreateComponent4"
create_component "CreateComponent5"
create_component "CreateComponent1"
create_component "CreateComponent2"
create_component "CreateComponent3"
create_component "CreateComponent1"
create_component "CreateComponent2"
create_component "CreateComponent3" sketch "SK_PDB-03-303_Deck_Standoff_M2_5x6_Body"
create_component "CreateComponent4" sketch "SK_PDB-03-304_PCB_Standoff_M2x4_Body"
create_component "CreateComponent1"
create_component "CreateComponent2"
create_component "CreateComponent3"
create_component "CreateComponent4"
create_component "CreateComponent5"
create_component "CreateComponent6"
create_component "CreateComponent1"
create_component "CreateComponent2"
create_component "CreateComponent3"
create_component "CreateComponent4"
